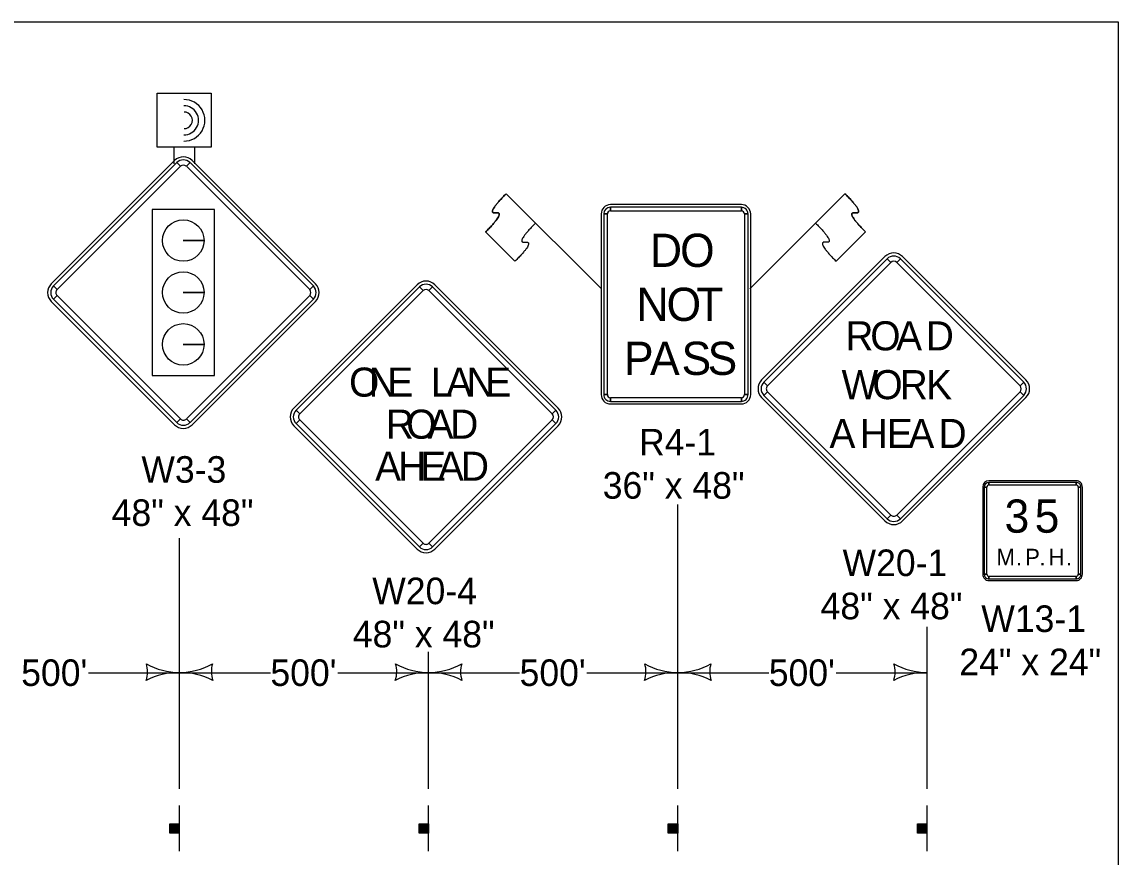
# Model space of a CAD drawing. Extents: x -2134934 to -2119606, y -2139046 to -2137036.
# Drawn here: x -2127757 to -2127097, y -2137539 to -2137036 of the extents above; entities that cross this region are included whole.
import ezdxf

# ---------------------------------------------------------------- set-up
doc = ezdxf.new("R2010")
doc.units = 0
for name, color, linetype in [('Default', 7, 'Continuous'), ('dsnStdLabel', 7, 'Continuous'), ('Level 2', 7, 'Continuous'), ('Level 5', 7, 'Continuous')]:
    doc.layers.add(name, color=color, linetype=linetype)

msp = doc.modelspace()

# ---------------------------------------------------------------- linework, layer by layer
at = {"layer": 'Default'}
msp.add_lwpolyline([(-2130231.95, -2137035.95), (-2127096.96, -2137035.95), (-2127096.96, -2139045.94), (-2130231.95, -2139045.94)], close=True, dxfattribs=at)
at = {"layer": 'dsnStdLabel'}
for p, q in [((-2127664.88, -2137119.33), (-2127739.13, -2137193.57)), ((-2127663.56, -2137120.65), (-2127661.35, -2137122.86)), ((-2127657.81, -2137122.86), (-2127655.6, -2137120.65)), ((-2127580.03, -2137193.57), (-2127654.28, -2137119.33)), ((-2127407.97, -2137196.68), (-2127465.31, -2137139.38)), ((-2127465.31, -2137139.38), (-2127447.62, -2137157.06)), ((-2127318.68, -2137196.68), (-2127261.36, -2137139.36)), ((-2127261.36, -2137139.36), (-2127279.05, -2137157.04)), ((-2127323.73, -2137145.92), (-2127402.48, -2137145.92)), ((-2127402.48, -2137149.67), (-2127402.48, -2137147.48)), ((-2127323.73, -2137147.48), (-2127323.73, -2137149.67)), ((-2127408.11, -2137151.54), (-2127408.11, -2137260.29)), ((-2127406.54, -2137151.54), (-2127404.36, -2137151.54)), ((-2127321.86, -2137151.54), (-2127319.67, -2137151.54)), ((-2127318.11, -2137260.29), (-2127318.11, -2137151.54)), ((-2127460, -2137180.05), (-2127477.68, -2137162.37)), ((-2127266.66, -2137180.03), (-2127248.99, -2137162.35)), ((-2127647.17, -2137167.55), (-2127659.67, -2137167.55)), ((-2127659.67, -2137167.55), (-2127647.17, -2137167.55)), ((-2127237.26, -2137177.23), (-2127311.51, -2137251.47)), ((-2127152.41, -2137251.47), (-2127226.65, -2137177.23)), ((-2127235.93, -2137178.55), (-2127233.72, -2137180.76)), ((-2127230.19, -2137180.76), (-2127227.98, -2137178.55)), ((-2127735.59, -2137197.11), (-2127737.8, -2137194.9)), ((-2127518.85, -2137194.14), (-2127593.09, -2137268.39)), ((-2127581.36, -2137194.9), (-2127583.56, -2137197.11)), ((-2127517.52, -2137195.47), (-2127515.31, -2137197.68)), ((-2127511.78, -2137197.68), (-2127509.57, -2137195.47)), ((-2127433.99, -2137268.39), (-2127508.24, -2137194.14)), ((-2127739.13, -2137204.18), (-2127664.88, -2137278.43)), ((-2127737.8, -2137202.85), (-2127735.59, -2137200.64)), ((-2127647.17, -2137198.8), (-2127659.67, -2137198.8)), ((-2127659.67, -2137198.8), (-2127647.17, -2137198.8)), ((-2127654.28, -2137278.43), (-2127580.03, -2137204.18)), ((-2127583.56, -2137200.64), (-2127581.36, -2137202.85)), ((-2127647.17, -2137230.05), (-2127659.67, -2137230.05)), ((-2127659.67, -2137230.05), (-2127647.17, -2137230.05)), ((-2127307.97, -2137255.01), (-2127310.18, -2137252.8)), ((-2127153.73, -2137252.8), (-2127155.94, -2137255.01)), ((-2127404.36, -2137260.29), (-2127406.54, -2137260.29)), ((-2127402.48, -2137264.35), (-2127402.48, -2137262.17)), ((-2127323.73, -2137262.17), (-2127323.73, -2137264.35)), ((-2127319.67, -2137260.29), (-2127321.86, -2137260.29)), ((-2127311.51, -2137262.08), (-2127237.26, -2137336.33)), ((-2127310.18, -2137260.75), (-2127307.97, -2137258.54)), ((-2127226.65, -2137336.33), (-2127152.41, -2137262.08)), ((-2127155.94, -2137258.54), (-2127153.73, -2137260.75)), ((-2127589.56, -2137271.93), (-2127591.77, -2137269.72)), ((-2127435.32, -2137269.72), (-2127437.53, -2137271.93)), ((-2127402.48, -2137265.92), (-2127323.73, -2137265.92)), ((-2127661.35, -2137274.89), (-2127663.56, -2137277.1)), ((-2127655.6, -2137277.1), (-2127657.81, -2137274.89)), ((-2127591.77, -2137277.67), (-2127589.56, -2137275.46)), ((-2127437.53, -2137275.46), (-2127435.32, -2137277.67)), ((-2127593.09, -2137279), (-2127518.85, -2137353.24)), ((-2127508.24, -2137353.24), (-2127433.99, -2137279)), ((-2127178.44, -2137315.92), (-2127178.44, -2137368.42)), ((-2127177.5, -2137315.92), (-2127175.94, -2137315.92)), ((-2127122.19, -2137312.17), (-2127174.69, -2137312.17)), ((-2127174.69, -2137314.67), (-2127174.69, -2137313.1)), ((-2127122.19, -2137313.1), (-2127122.19, -2137314.67)), ((-2127120.94, -2137315.92), (-2127119.37, -2137315.92)), ((-2127118.44, -2137368.42), (-2127118.44, -2137315.92)), ((-2127233.72, -2137332.79), (-2127235.93, -2137335)), ((-2127227.98, -2137335), (-2127230.19, -2137332.79)), ((-2127515.31, -2137349.71), (-2127517.52, -2137351.92)), ((-2127509.57, -2137351.92), (-2127511.78, -2137349.71)), ((-2127175.94, -2137368.42), (-2127177.5, -2137368.42)), ((-2127119.37, -2137368.42), (-2127120.94, -2137368.42)), ((-2127174.69, -2137371.23), (-2127174.69, -2137369.67)), ((-2127174.69, -2137372.17), (-2127122.19, -2137372.17)), ((-2127122.19, -2137369.67), (-2127122.19, -2137371.23))]:
    msp.add_line(p, q, dxfattribs=at)
for points in [[(-2127663.56, -2137120.65), (-2127737.8, -2137194.9), (-2127735.59, -2137197.11), (-2127661.35, -2137122.86), (-2127663.56, -2137120.65)], [(-2127581.36, -2137194.9), (-2127655.6, -2137120.65), (-2127657.81, -2137122.86), (-2127583.56, -2137197.11), (-2127581.36, -2137194.9)], [(-2127640.85, -2137148.93), (-2127678.31, -2137148.93), (-2127678.31, -2137248.82), (-2127640.85, -2137248.82), (-2127640.85, -2137148.93)], [(-2127323.73, -2137147.48), (-2127402.48, -2137147.48), (-2127402.48, -2137149.67), (-2127323.73, -2137149.67), (-2127323.73, -2137147.48)], [(-2127406.54, -2137151.54), (-2127406.54, -2137260.29), (-2127404.36, -2137260.29), (-2127404.36, -2137151.54), (-2127406.54, -2137151.54)], [(-2127319.67, -2137260.29), (-2127319.67, -2137151.54), (-2127321.86, -2137151.54), (-2127321.86, -2137260.29), (-2127319.67, -2137260.29)], [(-2127235.93, -2137178.55), (-2127310.18, -2137252.8), (-2127307.97, -2137255.01), (-2127233.72, -2137180.76), (-2127235.93, -2137178.55)], [(-2127153.73, -2137252.8), (-2127227.98, -2137178.55), (-2127230.19, -2137180.76), (-2127155.94, -2137255.01), (-2127153.73, -2137252.8)], [(-2127517.52, -2137195.47), (-2127591.77, -2137269.72), (-2127589.56, -2137271.93), (-2127515.31, -2137197.68), (-2127517.52, -2137195.47)], [(-2127435.32, -2137269.72), (-2127509.57, -2137195.47), (-2127511.78, -2137197.68), (-2127437.53, -2137271.93), (-2127435.32, -2137269.72)], [(-2127737.8, -2137202.85), (-2127663.56, -2137277.1), (-2127661.35, -2137274.89), (-2127735.59, -2137200.64), (-2127737.8, -2137202.85)], [(-2127655.6, -2137277.1), (-2127581.36, -2137202.85), (-2127583.56, -2137200.64), (-2127657.81, -2137274.89), (-2127655.6, -2137277.1)], [(-2127402.48, -2137264.35), (-2127323.73, -2137264.35), (-2127323.73, -2137262.17), (-2127402.48, -2137262.17), (-2127402.48, -2137264.35)], [(-2127310.18, -2137260.75), (-2127235.93, -2137335), (-2127233.72, -2137332.79), (-2127307.97, -2137258.54), (-2127310.18, -2137260.75)], [(-2127227.98, -2137335), (-2127153.73, -2137260.75), (-2127155.94, -2137258.54), (-2127230.19, -2137332.79), (-2127227.98, -2137335)], [(-2127591.77, -2137277.67), (-2127517.52, -2137351.92), (-2127515.31, -2137349.71), (-2127589.56, -2137275.46), (-2127591.77, -2137277.67)], [(-2127509.57, -2137351.92), (-2127435.32, -2137277.67), (-2127437.53, -2137275.46), (-2127511.78, -2137349.71), (-2127509.57, -2137351.92)], [(-2127177.5, -2137315.92), (-2127177.5, -2137368.42), (-2127175.94, -2137368.42), (-2127175.94, -2137315.92), (-2127177.5, -2137315.92)], [(-2127122.19, -2137313.1), (-2127174.69, -2137313.1), (-2127174.69, -2137314.67), (-2127122.19, -2137314.67), (-2127122.19, -2137313.1)], [(-2127119.37, -2137368.42), (-2127119.37, -2137315.92), (-2127120.94, -2137315.92), (-2127120.94, -2137368.42), (-2127119.37, -2137368.42)], [(-2127174.69, -2137371.23), (-2127122.19, -2137371.23), (-2127122.19, -2137369.67), (-2127174.69, -2137369.67), (-2127174.69, -2137371.23)]]:
    msp.add_lwpolyline(points, close=True, dxfattribs=at)
for centre in [(-2127659.67, -2137167.55), (-2127659.67, -2137198.8), (-2127659.67, -2137230.05)]:
    msp.add_circle(centre, 12.5, dxfattribs=at)
for centre, radius, start, end in [((-2127659.58, -2137124.63), 7.5, 44.99999, 134.99974), ((-2127659.58, -2137124.63), 5.62, 44.99999, 134.99974), ((-2127659.58, -2137124.63), 2.5, 44.99999, 134.99974), ((-2127402.48, -2137151.54), 5.62, 90.00021, 179.99985), ((-2127402.48, -2137151.54), 4.06, 90.00021, 179.99985), ((-2127402.48, -2137151.54), 1.87, 90.00021, 179.99985), ((-2127323.73, -2137151.54), 5.62, 0, 90.00021), ((-2127323.73, -2137151.54), 4.06, 0, 90.00021), ((-2127323.73, -2137151.54), 1.87, 0, 90.00021), ((-2127231.96, -2137182.53), 7.5, 44.99999, 134.99974), ((-2127231.96, -2137182.53), 5.62, 44.99999, 134.99974), ((-2127231.96, -2137182.53), 2.5, 44.99999, 134.99974), ((-2127733.83, -2137198.88), 7.5, 134.99974, 224.99995), ((-2127733.83, -2137198.88), 5.62, 134.99974, 224.99995), ((-2127733.83, -2137198.88), 2.5, 134.99974, 224.99995), ((-2127585.33, -2137198.88), 2.5, 315.00016, 44.9998), ((-2127585.33, -2137198.88), 5.62, 315.00016, 44.9998), ((-2127585.33, -2137198.88), 7.5, 315.00016, 44.9998), ((-2127513.54, -2137199.45), 7.5, 44.99999, 134.99974), ((-2127513.54, -2137199.45), 5.62, 44.99999, 134.99974), ((-2127513.54, -2137199.45), 2.5, 44.99999, 134.99974), ((-2127306.2, -2137256.78), 7.5, 134.99974, 224.99995), ((-2127306.2, -2137256.78), 5.62, 134.99974, 224.99995), ((-2127306.2, -2137256.78), 2.5, 134.99974, 224.99995), ((-2127157.71, -2137256.78), 2.5, 315.00016, 44.9998), ((-2127157.71, -2137256.78), 5.62, 315.00016, 44.9998), ((-2127157.71, -2137256.78), 7.5, 315.00016, 44.9998), ((-2127402.48, -2137260.29), 5.62, 179.99985, 270.00006), ((-2127402.48, -2137260.29), 4.06, 179.99985, 270.00006), ((-2127402.48, -2137260.29), 1.87, 179.99985, 270.00006), ((-2127323.73, -2137260.29), 5.62, 270.00006, 0.00027), ((-2127323.73, -2137260.29), 4.06, 270.00006, 0.00027), ((-2127323.73, -2137260.29), 1.87, 270.00006, 0.00027), ((-2127587.79, -2137273.69), 7.5, 134.99974, 224.99995), ((-2127587.79, -2137273.69), 5.62, 134.99974, 224.99995), ((-2127439.3, -2137273.69), 5.62, 315.00016, 44.9998), ((-2127439.3, -2137273.69), 7.5, 315.00016, 44.9998), ((-2127659.58, -2137273.12), 2.5, 224.99995, 315.00016), ((-2127587.79, -2137273.69), 2.5, 134.99974, 224.99995), ((-2127439.3, -2137273.69), 2.5, 315.00016, 44.9998), ((-2127659.58, -2137273.12), 7.5, 224.99995, 315.00016), ((-2127659.58, -2137273.12), 5.62, 224.99995, 315.00016), ((-2127174.69, -2137315.92), 3.75, 90.00021, 179.99985), ((-2127174.69, -2137315.92), 2.81, 90.00021, 179.99985), ((-2127174.69, -2137315.92), 1.25, 90.00021, 179.99985), ((-2127122.19, -2137315.92), 3.75, 0, 90.00021), ((-2127122.19, -2137315.92), 2.81, 0, 90.00021), ((-2127122.19, -2137315.92), 1.25, 0, 90.00021), ((-2127231.96, -2137331.02), 5.62, 224.99995, 315.00016), ((-2127231.96, -2137331.02), 2.5, 224.99995, 315.00016), ((-2127231.96, -2137331.02), 7.5, 224.99995, 315.00016), ((-2127513.54, -2137347.94), 7.5, 224.99995, 315.00016), ((-2127513.54, -2137347.94), 5.62, 224.99995, 315.00016), ((-2127513.54, -2137347.94), 2.5, 224.99995, 315.00016), ((-2127174.69, -2137368.42), 3.75, 179.99985, 270.00006), ((-2127174.69, -2137368.42), 2.81, 179.99985, 270.00006), ((-2127174.69, -2137368.42), 1.25, 179.99985, 270.00006), ((-2127122.19, -2137368.42), 3.75, 270.00006, 0.00027), ((-2127122.19, -2137368.42), 2.81, 270.00006, 0.00027), ((-2127122.19, -2137368.42), 1.25, 270.00006, 0.00027)]:
    msp.add_arc(centre, radius, start, end, dxfattribs=at)
for points in [[(-2127477.68, -2137162.37), (-2127465.31, -2137149.99), (-2127477.68, -2137151.77), (-2127465.31, -2137139.38)], [(-2127248.99, -2137162.35), (-2127261.36, -2137149.98), (-2127248.99, -2137151.75), (-2127261.36, -2137139.36)], [(-2127447.62, -2137157.06), (-2127460, -2137169.44), (-2127447.63, -2137167.67), (-2127460, -2137180.05)], [(-2127279.05, -2137157.04), (-2127266.67, -2137169.43), (-2127279.04, -2137167.66), (-2127266.66, -2137180.03)]]:
    msp.add_open_spline(points, degree=2, dxfattribs=at)
at = {"layer": 'Level 2'}
for p, q in [((-2127665.42, -2137111.41), (-2127665.42, -2137121.41)), ((-2127652.92, -2137111.41), (-2127652.92, -2137121.41)), ((-2127361.96, -2137497.66), (-2127361.96, -2137326.42)), ((-2127661.96, -2137497.66), (-2127661.96, -2137346.75)), ((-2127211.96, -2137497.66), (-2127211.96, -2137399.97)), ((-2127511.96, -2137497.66), (-2127511.96, -2137415.16)), ((-2127716.71, -2137427.66), (-2127661.96, -2137427.66)), ((-2127661.96, -2137427.66), (-2127607.21, -2137427.66)), ((-2127566.71, -2137427.66), (-2127511.96, -2137427.66)), ((-2127511.96, -2137427.66), (-2127457.21, -2137427.66)), ((-2127416.71, -2137427.66), (-2127361.96, -2137427.66)), ((-2127361.96, -2137427.66), (-2127307.21, -2137427.66)), ((-2127266.71, -2137427.66), (-2127211.96, -2137427.66)), ((-2127661.96, -2137535.16), (-2127661.96, -2137507.66)), ((-2127511.96, -2137535.16), (-2127511.96, -2137507.66)), ((-2127361.96, -2137535.16), (-2127361.96, -2137507.66)), ((-2127211.96, -2137535.16), (-2127211.96, -2137507.66)), ((-2127667.28, -2137524.3), (-2127667.28, -2137518.71)), ((-2127666.96, -2137518.71), (-2127666.96, -2137524.3)), ((-2127666.74, -2137524.3), (-2127666.74, -2137518.71)), ((-2127666.42, -2137518.71), (-2127666.42, -2137524.3)), ((-2127666.19, -2137524.3), (-2127666.21, -2137518.71)), ((-2127665.78, -2137518.71), (-2127665.76, -2137524.3)), ((-2127665.56, -2137524.3), (-2127665.56, -2137518.71)), ((-2127665.13, -2137518.71), (-2127665.13, -2137524.3)), ((-2127664.75, -2137524.3), (-2127664.75, -2137518.71)), ((-2127664.43, -2137518.71), (-2127664.41, -2137524.3)), ((-2127664.21, -2137524.3), (-2127664.21, -2137518.71)), ((-2127663.94, -2137518.71), (-2127663.94, -2137524.3)), ((-2127663.61, -2137524.3), (-2127663.61, -2137518.71)), ((-2127663.4, -2137518.71), (-2127663.4, -2137524.3)), ((-2127663.18, -2137524.3), (-2127663.18, -2137518.71)), ((-2127662.91, -2137518.71), (-2127662.91, -2137524.3)), ((-2127662.65, -2137524.3), (-2127662.65, -2137518.71)), ((-2127662.37, -2137518.71), (-2127662.37, -2137524.3)), ((-2127517.28, -2137524.3), (-2127517.28, -2137518.71)), ((-2127516.96, -2137518.71), (-2127516.96, -2137524.3)), ((-2127516.74, -2137524.3), (-2127516.74, -2137518.71)), ((-2127516.42, -2137518.71), (-2127516.42, -2137524.3)), ((-2127516.19, -2137524.3), (-2127516.21, -2137518.71)), ((-2127515.78, -2137518.71), (-2127515.76, -2137524.3)), ((-2127515.56, -2137524.3), (-2127515.56, -2137518.71)), ((-2127515.13, -2137518.71), (-2127515.13, -2137524.3)), ((-2127514.75, -2137524.3), (-2127514.75, -2137518.71)), ((-2127514.43, -2137518.71), (-2127514.41, -2137524.3)), ((-2127514.21, -2137524.3), (-2127514.21, -2137518.71)), ((-2127513.94, -2137518.71), (-2127513.94, -2137524.3)), ((-2127513.61, -2137524.3), (-2127513.61, -2137518.71)), ((-2127513.4, -2137518.71), (-2127513.4, -2137524.3)), ((-2127513.18, -2137524.3), (-2127513.18, -2137518.71)), ((-2127512.91, -2137518.71), (-2127512.91, -2137524.3)), ((-2127512.65, -2137524.3), (-2127512.65, -2137518.71)), ((-2127512.37, -2137518.71), (-2127512.37, -2137524.3)), ((-2127367.28, -2137524.3), (-2127367.28, -2137518.71)), ((-2127366.96, -2137518.71), (-2127366.96, -2137524.3)), ((-2127366.74, -2137524.3), (-2127366.74, -2137518.71)), ((-2127366.42, -2137518.71), (-2127366.42, -2137524.3)), ((-2127366.19, -2137524.3), (-2127366.21, -2137518.71)), ((-2127365.78, -2137518.71), (-2127365.76, -2137524.3)), ((-2127365.56, -2137524.3), (-2127365.56, -2137518.71)), ((-2127365.13, -2137518.71), (-2127365.13, -2137524.3)), ((-2127364.75, -2137524.3), (-2127364.75, -2137518.71)), ((-2127364.43, -2137518.71), (-2127364.41, -2137524.3)), ((-2127364.21, -2137524.3), (-2127364.21, -2137518.71)), ((-2127363.94, -2137518.71), (-2127363.94, -2137524.3)), ((-2127363.61, -2137524.3), (-2127363.61, -2137518.71)), ((-2127363.4, -2137518.71), (-2127363.4, -2137524.3)), ((-2127363.18, -2137524.3), (-2127363.18, -2137518.71)), ((-2127362.91, -2137518.71), (-2127362.91, -2137524.3)), ((-2127362.65, -2137524.3), (-2127362.65, -2137518.71)), ((-2127362.37, -2137518.71), (-2127362.37, -2137524.3)), ((-2127217.28, -2137524.3), (-2127217.28, -2137518.71)), ((-2127216.96, -2137518.71), (-2127216.96, -2137524.3)), ((-2127216.74, -2137524.3), (-2127216.74, -2137518.71)), ((-2127216.42, -2137518.71), (-2127216.42, -2137524.3)), ((-2127216.2, -2137524.3), (-2127216.21, -2137518.71)), ((-2127215.78, -2137518.71), (-2127215.76, -2137524.3)), ((-2127215.56, -2137524.3), (-2127215.56, -2137518.71)), ((-2127215.13, -2137518.71), (-2127215.13, -2137524.3)), ((-2127214.75, -2137524.3), (-2127214.75, -2137518.71)), ((-2127214.43, -2137518.71), (-2127214.41, -2137524.3)), ((-2127214.21, -2137524.3), (-2127214.21, -2137518.71)), ((-2127213.94, -2137518.71), (-2127213.94, -2137524.3)), ((-2127213.61, -2137524.3), (-2127213.61, -2137518.71)), ((-2127213.4, -2137518.71), (-2127213.4, -2137524.3)), ((-2127213.18, -2137524.3), (-2127213.18, -2137518.71)), ((-2127212.91, -2137518.71), (-2127212.91, -2137524.3)), ((-2127212.65, -2137524.3), (-2127212.65, -2137518.71)), ((-2127212.37, -2137518.71), (-2127212.37, -2137524.3))]:
    msp.add_line(p, q, dxfattribs=at)
for points in [[(-2127675.42, -2137111.41), (-2127675.42, -2137078.91), (-2127642.92, -2137078.91), (-2127642.92, -2137111.41)], [(-2127662.05, -2137518.71), (-2127662.05, -2137524.34), (-2127667.68, -2137524.34), (-2127667.68, -2137518.71)], [(-2127512.05, -2137518.71), (-2127512.05, -2137524.34), (-2127517.68, -2137524.34), (-2127517.68, -2137518.71)], [(-2127362.05, -2137518.71), (-2127362.05, -2137524.34), (-2127367.68, -2137524.34), (-2127367.68, -2137518.71)], [(-2127212.05, -2137518.71), (-2127212.05, -2137524.34), (-2127217.68, -2137524.34), (-2127217.68, -2137518.71)]]:
    msp.add_lwpolyline(points, close=True, dxfattribs=at)
for centre, radius, start, end in [((-2127659.16, -2137095.18), 12.5, 269.40414, 90.54446), ((-2127659.16, -2137095.18), 12.5, 269.40414, 90.54446), ((-2127659.16, -2137095.18), 8.75, 269.40414, 90.54446), ((-2127659.16, -2137095.18), 5, 269.40414, 90.54446), ((-2127697.57, -2137427.04), 16.42, 341.26665, 16.73335), ((-2127662.68, -2137470.15), 42.5, 89.0176, 117.07249), ((-2127661.2, -2137385.17), 42.5, 240.92751, 268.9824), ((-2127662.71, -2137385.17), 42.5, 271.0176, 299.07249), ((-2127661.23, -2137470.15), 42.5, 62.92751, 90.9824), ((-2127626.34, -2137427.04), 16.42, 163.26665, 198.73335), ((-2127547.57, -2137427.04), 16.42, 341.26665, 16.73335), ((-2127512.68, -2137470.15), 42.5, 89.0176, 117.07249), ((-2127511.2, -2137385.17), 42.5, 240.92751, 268.9824), ((-2127512.71, -2137385.17), 42.5, 271.0176, 299.07249), ((-2127511.23, -2137470.15), 42.5, 62.92751, 90.9824), ((-2127476.34, -2137427.04), 16.42, 163.26665, 198.73335), ((-2127397.57, -2137427.04), 16.42, 341.26665, 16.73335), ((-2127362.68, -2137470.15), 42.5, 89.0176, 117.07249), ((-2127361.2, -2137385.17), 42.5, 240.92751, 268.9824), ((-2127362.71, -2137385.17), 42.5, 271.0176, 299.07249), ((-2127361.23, -2137470.15), 42.5, 62.92751, 90.9824), ((-2127326.34, -2137427.04), 16.42, 163.26665, 198.73335), ((-2127247.57, -2137427.04), 16.42, 341.26665, 16.73335), ((-2127212.68, -2137470.15), 42.5, 89.0176, 117.07249), ((-2127211.2, -2137385.17), 42.5, 240.92751, 268.9824)]:
    msp.add_arc(centre, radius, start, end, dxfattribs=at)
at = {"layer": 'Level 5'}
for p, q in [((-2127477.68, -2137162.37), (-2127460, -2137180.05)), ((-2127248.99, -2137162.35), (-2127266.66, -2137180.03))]:
    msp.add_line(p, q, dxfattribs=at)
for points in [[(-2127465.31, -2137139.38), (-2127477.68, -2137151.77), (-2127465.31, -2137149.99), (-2127477.68, -2137162.37)], [(-2127261.36, -2137139.36), (-2127248.99, -2137151.75), (-2127261.36, -2137149.98), (-2127248.99, -2137162.35)], [(-2127447.62, -2137157.06), (-2127460, -2137169.44), (-2127447.63, -2137167.67), (-2127460, -2137180.05)], [(-2127279.05, -2137157.04), (-2127266.67, -2137169.43), (-2127279.04, -2137167.66), (-2127266.66, -2137180.03)]]:
    msp.add_open_spline(points, degree=2, dxfattribs=at)

# ---------------------------------------------------------------- texts
at = {"layer": 'dsnStdLabel'}
for s, height, p in [('D', 20, (-2127378.73, -2137183.42)), ('O', 20, (-2127360.61, -2137183.42)), ('N', 20, (-2127386.86, -2137215.92)), ('O', 20, (-2127368.73, -2137215.92)), ('T', 20, (-2127350.92, -2137215.92)), ('R', 17.5, (-2127261.12, -2137233.65)), ('O', 17.5, (-2127246.11, -2137233.65)), ('A', 17.5, (-2127230.56, -2137233.65)), ('D', 17.5, (-2127212.68, -2137233.65)), ('P', 20, (-2127394.37, -2137248.42)), ('A', 20, (-2127378.69, -2137248.42)), ('S', 20, (-2127359.72, -2137248.42)), ('S', 20, (-2127344.03, -2137248.42)), ('O', 17.5, (-2127559.83, -2137261.51)), ('N', 17.5, (-2127548.05, -2137261.51)), ('E', 17.5, (-2127536.83, -2137261.51)), ('L', 17.5, (-2127510.58, -2137261.51)), ('A', 17.5, (-2127501.38, -2137261.51)), ('N', 17.5, (-2127489.11, -2137261.51)), ('E', 17.5, (-2127477.88, -2137261.51)), ('W', 17.5, (-2127263.4, -2137263.03)), ('O', 17.5, (-2127244.81, -2137263.03)), ('R', 17.5, (-2127228.4, -2137263.03)), ('K', 17.5, (-2127212.54, -2137263.03)), ('R', 17.5, (-2127537.72, -2137286.82)), ('O', 17.5, (-2127525.43, -2137286.82)), ('A', 17.5, (-2127512.59, -2137286.82)), ('D', 17.5, (-2127498.94, -2137286.82)), ('A', 17.5, (-2127270.68, -2137292.4)), ('H', 17.5, (-2127252.47, -2137292.4)), ('E', 17.5, (-2127236.24, -2137292.4)), ('A', 17.5, (-2127223.2, -2137292.4)), ('D', 17.5, (-2127204.99, -2137292.4)), ('R4-1', 16, (-2127385.27, -2137296.92)), ('A', 17.5, (-2127544.16, -2137312.13)), ('H', 17.5, (-2127530.29, -2137312.13)), ('E', 17.5, (-2127517.08, -2137312.13)), ('A', 17.5, (-2127506.36, -2137312.13)), ('D', 17.5, (-2127492.5, -2137312.13)), ('W3-3', 16, (-2127684.87, -2137313.34)), ('36" x 48"', 16, (-2127407.17, -2137322.92)), ('48" x 48"', 16, (-2127702.75, -2137339.34)), ('3', 20, (-2127165.29, -2137343.41)), ('5', 20, (-2127147.16, -2137343.41)), ('W20-1', 16, (-2127262.81, -2137369.52)), ('M', 10, (-2127170.21, -2137363.1)), ('P', 10, (-2127152.96, -2137363.1)), ('H', 10, (-2127138.84, -2137363.1)), ('.', 10, (-2127158.42, -2137363.1)), ('.', 10, (-2127144.3, -2137363.1)), ('.', 10, (-2127128.37, -2137363.1)), ('W20-4', 16, (-2127545.91, -2137386.44)), ('48" x 48"', 16, (-2127276.02, -2137395.52)), ('W13-1', 16, (-2127179.29, -2137403.17)), ('48" x 48"', 16, (-2127557.61, -2137412.44)), ('24" x 24"', 16, (-2127192.5, -2137429.17))]:
    msp.add_text(s, height=height, dxfattribs=at).set_placement(p)
at = {"layer": 'Level 2'}
for p in [(-2127757.21, -2137435.66), (-2127607.21, -2137435.66), (-2127457.21, -2137435.66), (-2127307.21, -2137435.66)]:
    msp.add_text("500'", height=16, dxfattribs=at).set_placement(p)

doc.saveas('drawing.dxf')
